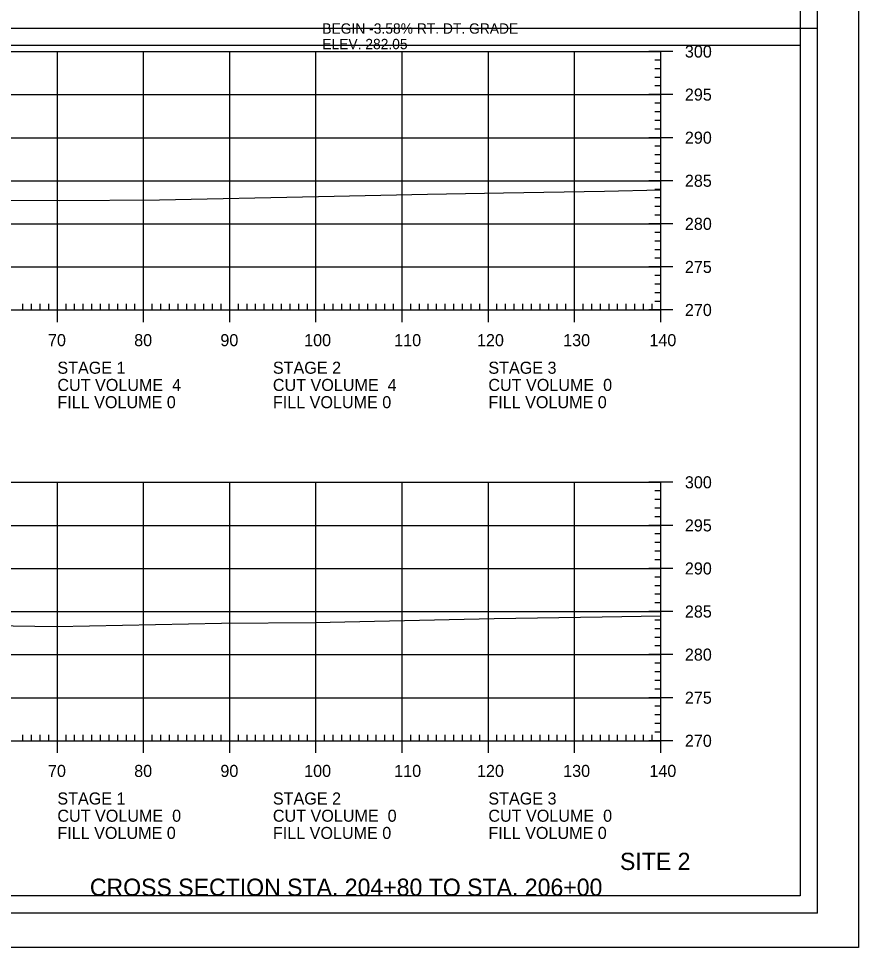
# Model space of a CAD drawing. Extents: x 1368713 to 1370673, y 380279 to 380950.
# Drawn here: x 1370575.1 to 1370672.6, y 380310.4 to 380418.2 of the extents above; entities that cross this region are included whole.
import ezdxf

# ---------------------------------------------------------------- set-up
doc = ezdxf.new("R2010")
doc.units = 0
for name, color, linetype in [('Notes', 7, 'Continuous'), ('R_Axis', 7, 'Continuous'), ('R_Axis Annot', 7, 'Continuous'), ('R_Border', 7, 'Continuous'), ('R_Border Plan-Plan', 7, 'Continuous'), ('R_Draft', 7, 'Continuous'), ('R_Exist Surface', 7, 'Continuous'), ('R_Grid', 7, 'Continuous'), ('R_No Plot', 7, 'Continuous')]:
    doc.layers.add(name, color=color, linetype=linetype)

msp = doc.modelspace()

# ---------------------------------------------------------------- linework, layer by layer
at = {"layer": 'R_Axis'}
for p, q in [((1370651.03, 380414.42), (1370648.23, 380414.42)), ((1370649.63, 380384.42), (1370649.63, 380414.42)), ((1370649.63, 380413.42), (1370648.93, 380413.42)), ((1370649.63, 380412.42), (1370648.93, 380412.42)), ((1370649.63, 380411.42), (1370648.93, 380411.42)), ((1370649.63, 380410.42), (1370648.93, 380410.42)), ((1370651.03, 380409.42), (1370648.23, 380409.42)), ((1370649.63, 380408.42), (1370648.93, 380408.42)), ((1370649.63, 380407.42), (1370648.93, 380407.42)), ((1370649.63, 380406.42), (1370648.93, 380406.42)), ((1370649.63, 380405.42), (1370648.93, 380405.42)), ((1370651.03, 380404.42), (1370648.23, 380404.42)), ((1370649.63, 380403.42), (1370648.93, 380403.42)), ((1370649.63, 380402.42), (1370648.93, 380402.42)), ((1370649.63, 380401.42), (1370648.93, 380401.42)), ((1370651.03, 380399.42), (1370648.23, 380399.42)), ((1370649.63, 380400.42), (1370648.93, 380400.42)), ((1370649.63, 380398.42), (1370648.93, 380398.42)), ((1370649.63, 380397.42), (1370648.93, 380397.42)), ((1370649.63, 380396.42), (1370648.93, 380396.42)), ((1370649.63, 380395.42), (1370648.93, 380395.42)), ((1370651.03, 380394.42), (1370648.23, 380394.42)), ((1370649.63, 380393.42), (1370648.93, 380393.42)), ((1370649.63, 380392.42), (1370648.93, 380392.42)), ((1370649.63, 380391.42), (1370648.93, 380391.42)), ((1370649.63, 380390.42), (1370648.93, 380390.42)), ((1370651.03, 380389.42), (1370648.23, 380389.42)), ((1370649.63, 380388.42), (1370648.93, 380388.42)), ((1370649.63, 380387.42), (1370648.93, 380387.42)), ((1370579.63, 380383.02), (1370579.63, 380385.82)), ((1370589.63, 380383.02), (1370589.63, 380385.82)), ((1370599.63, 380383.02), (1370599.63, 380385.82)), ((1370609.63, 380383.02), (1370609.63, 380385.82)), ((1370619.63, 380383.02), (1370619.63, 380385.82)), ((1370629.63, 380383.02), (1370629.63, 380385.82)), ((1370639.63, 380383.02), (1370639.63, 380385.82)), ((1370649.63, 380386.42), (1370648.93, 380386.42)), ((1370649.63, 380385.42), (1370648.93, 380385.42)), ((1370649.63, 380383.02), (1370649.63, 380385.82)), ((1370369.63, 380384.42), (1370649.63, 380384.42)), ((1370575.63, 380384.42), (1370575.63, 380385.12)), ((1370576.63, 380384.42), (1370576.63, 380385.12)), ((1370577.63, 380384.42), (1370577.63, 380385.12)), ((1370578.63, 380384.42), (1370578.63, 380385.12)), ((1370580.63, 380384.42), (1370580.63, 380385.12)), ((1370581.63, 380384.42), (1370581.63, 380385.12)), ((1370582.63, 380384.42), (1370582.63, 380385.12)), ((1370583.63, 380384.42), (1370583.63, 380385.12)), ((1370584.63, 380384.42), (1370584.63, 380385.12)), ((1370585.63, 380384.42), (1370585.63, 380385.12)), ((1370586.63, 380384.42), (1370586.63, 380385.12)), ((1370587.63, 380384.42), (1370587.63, 380385.12)), ((1370588.63, 380384.42), (1370588.63, 380385.12)), ((1370590.63, 380384.42), (1370590.63, 380385.12)), ((1370591.63, 380384.42), (1370591.63, 380385.12)), ((1370592.63, 380384.42), (1370592.63, 380385.12)), ((1370593.63, 380384.42), (1370593.63, 380385.12)), ((1370594.63, 380384.42), (1370594.63, 380385.12)), ((1370595.63, 380384.42), (1370595.63, 380385.12)), ((1370596.63, 380384.42), (1370596.63, 380385.12)), ((1370597.63, 380384.42), (1370597.63, 380385.12)), ((1370598.63, 380384.42), (1370598.63, 380385.12)), ((1370600.63, 380384.42), (1370600.63, 380385.12)), ((1370601.63, 380384.42), (1370601.63, 380385.12)), ((1370602.63, 380384.42), (1370602.63, 380385.12)), ((1370603.63, 380384.42), (1370603.63, 380385.12)), ((1370604.63, 380384.42), (1370604.63, 380385.12)), ((1370605.63, 380384.42), (1370605.63, 380385.12)), ((1370606.63, 380384.42), (1370606.63, 380385.12)), ((1370607.63, 380384.42), (1370607.63, 380385.12)), ((1370608.63, 380384.42), (1370608.63, 380385.12)), ((1370610.63, 380384.42), (1370610.63, 380385.12)), ((1370611.63, 380384.42), (1370611.63, 380385.12)), ((1370612.63, 380384.42), (1370612.63, 380385.12)), ((1370613.63, 380384.42), (1370613.63, 380385.12)), ((1370614.63, 380384.42), (1370614.63, 380385.12)), ((1370615.63, 380384.42), (1370615.63, 380385.12)), ((1370616.63, 380384.42), (1370616.63, 380385.12)), ((1370617.63, 380384.42), (1370617.63, 380385.12)), ((1370618.63, 380384.42), (1370618.63, 380385.12)), ((1370620.63, 380384.42), (1370620.63, 380385.12)), ((1370621.63, 380384.42), (1370621.63, 380385.12)), ((1370622.63, 380384.42), (1370622.63, 380385.12)), ((1370623.63, 380384.42), (1370623.63, 380385.12)), ((1370624.63, 380384.42), (1370624.63, 380385.12)), ((1370625.63, 380384.42), (1370625.63, 380385.12)), ((1370626.63, 380384.42), (1370626.63, 380385.12)), ((1370627.63, 380384.42), (1370627.63, 380385.12)), ((1370628.63, 380384.42), (1370628.63, 380385.12)), ((1370630.63, 380384.42), (1370630.63, 380385.12)), ((1370631.63, 380384.42), (1370631.63, 380385.12)), ((1370632.63, 380384.42), (1370632.63, 380385.12)), ((1370633.63, 380384.42), (1370633.63, 380385.12)), ((1370634.63, 380384.42), (1370634.63, 380385.12)), ((1370635.63, 380384.42), (1370635.63, 380385.12)), ((1370636.63, 380384.42), (1370636.63, 380385.12)), ((1370637.63, 380384.42), (1370637.63, 380385.12)), ((1370638.63, 380384.42), (1370638.63, 380385.12)), ((1370640.63, 380384.42), (1370640.63, 380385.12)), ((1370641.63, 380384.42), (1370641.63, 380385.12)), ((1370642.63, 380384.42), (1370642.63, 380385.12)), ((1370643.63, 380384.42), (1370643.63, 380385.12)), ((1370644.63, 380384.42), (1370644.63, 380385.12)), ((1370645.63, 380384.42), (1370645.63, 380385.12)), ((1370646.63, 380384.42), (1370646.63, 380385.12)), ((1370647.63, 380384.42), (1370647.63, 380385.12)), ((1370651.03, 380384.42), (1370648.23, 380384.42)), ((1370648.63, 380384.42), (1370648.63, 380385.12)), ((1370651.03, 380364.42), (1370648.23, 380364.42)), ((1370649.63, 380334.42), (1370649.63, 380364.42)), ((1370649.63, 380363.42), (1370648.93, 380363.42)), ((1370649.63, 380362.42), (1370648.93, 380362.42)), ((1370649.63, 380361.42), (1370648.93, 380361.42)), ((1370649.63, 380360.42), (1370648.93, 380360.42)), ((1370651.03, 380359.42), (1370648.23, 380359.42)), ((1370649.63, 380358.42), (1370648.93, 380358.42)), ((1370649.63, 380357.42), (1370648.93, 380357.42)), ((1370649.63, 380356.42), (1370648.93, 380356.42)), ((1370649.63, 380355.42), (1370648.93, 380355.42)), ((1370651.03, 380354.42), (1370648.23, 380354.42)), ((1370649.63, 380353.42), (1370648.93, 380353.42)), ((1370649.63, 380352.42), (1370648.93, 380352.42)), ((1370649.63, 380351.42), (1370648.93, 380351.42)), ((1370649.63, 380350.42), (1370648.93, 380350.42)), ((1370651.03, 380349.42), (1370648.23, 380349.42)), ((1370649.63, 380348.42), (1370648.93, 380348.42)), ((1370649.63, 380347.42), (1370648.93, 380347.42)), ((1370649.63, 380346.42), (1370648.93, 380346.42)), ((1370649.63, 380345.42), (1370648.93, 380345.42)), ((1370651.03, 380344.42), (1370648.23, 380344.42)), ((1370649.63, 380343.42), (1370648.93, 380343.42)), ((1370649.63, 380342.42), (1370648.93, 380342.42)), ((1370649.63, 380341.42), (1370648.93, 380341.42)), ((1370649.63, 380340.42), (1370648.93, 380340.42)), ((1370651.03, 380339.42), (1370648.23, 380339.42)), ((1370649.63, 380338.42), (1370648.93, 380338.42)), ((1370649.63, 380337.42), (1370648.93, 380337.42)), ((1370579.63, 380333.02), (1370579.63, 380335.82)), ((1370589.63, 380333.02), (1370589.63, 380335.82)), ((1370599.63, 380333.02), (1370599.63, 380335.82)), ((1370609.63, 380333.02), (1370609.63, 380335.82)), ((1370619.63, 380333.02), (1370619.63, 380335.82)), ((1370629.63, 380333.02), (1370629.63, 380335.82)), ((1370639.63, 380333.02), (1370639.63, 380335.82)), ((1370649.63, 380336.42), (1370648.93, 380336.42)), ((1370649.63, 380333.02), (1370649.63, 380335.82)), ((1370575.63, 380334.42), (1370575.63, 380335.12)), ((1370576.63, 380334.42), (1370576.63, 380335.12)), ((1370577.63, 380334.42), (1370577.63, 380335.12)), ((1370578.63, 380334.42), (1370578.63, 380335.12)), ((1370580.63, 380334.42), (1370580.63, 380335.12)), ((1370581.63, 380334.42), (1370581.63, 380335.12)), ((1370582.63, 380334.42), (1370582.63, 380335.12)), ((1370583.63, 380334.42), (1370583.63, 380335.12)), ((1370584.63, 380334.42), (1370584.63, 380335.12)), ((1370585.63, 380334.42), (1370585.63, 380335.12)), ((1370586.63, 380334.42), (1370586.63, 380335.12)), ((1370587.63, 380334.42), (1370587.63, 380335.12)), ((1370588.63, 380334.42), (1370588.63, 380335.12)), ((1370590.63, 380334.42), (1370590.63, 380335.12)), ((1370591.63, 380334.42), (1370591.63, 380335.12)), ((1370592.63, 380334.42), (1370592.63, 380335.12)), ((1370593.63, 380334.42), (1370593.63, 380335.12)), ((1370594.63, 380334.42), (1370594.63, 380335.12)), ((1370595.63, 380334.42), (1370595.63, 380335.12)), ((1370596.63, 380334.42), (1370596.63, 380335.12)), ((1370597.63, 380334.42), (1370597.63, 380335.12)), ((1370598.63, 380334.42), (1370598.63, 380335.12)), ((1370600.63, 380334.42), (1370600.63, 380335.12)), ((1370601.63, 380334.42), (1370601.63, 380335.12)), ((1370602.63, 380334.42), (1370602.63, 380335.12)), ((1370603.63, 380334.42), (1370603.63, 380335.12)), ((1370604.63, 380334.42), (1370604.63, 380335.12)), ((1370605.63, 380334.42), (1370605.63, 380335.12)), ((1370606.63, 380334.42), (1370606.63, 380335.12)), ((1370607.63, 380334.42), (1370607.63, 380335.12)), ((1370608.63, 380334.42), (1370608.63, 380335.12)), ((1370610.63, 380334.42), (1370610.63, 380335.12)), ((1370611.63, 380334.42), (1370611.63, 380335.12)), ((1370612.63, 380334.42), (1370612.63, 380335.12)), ((1370613.63, 380334.42), (1370613.63, 380335.12)), ((1370614.63, 380334.42), (1370614.63, 380335.12)), ((1370615.63, 380334.42), (1370615.63, 380335.12)), ((1370616.63, 380334.42), (1370616.63, 380335.12)), ((1370617.63, 380334.42), (1370617.63, 380335.12)), ((1370618.63, 380334.42), (1370618.63, 380335.12)), ((1370620.63, 380334.42), (1370620.63, 380335.12)), ((1370621.63, 380334.42), (1370621.63, 380335.12)), ((1370622.63, 380334.42), (1370622.63, 380335.12)), ((1370623.63, 380334.42), (1370623.63, 380335.12)), ((1370624.63, 380334.42), (1370624.63, 380335.12)), ((1370625.63, 380334.42), (1370625.63, 380335.12)), ((1370626.63, 380334.42), (1370626.63, 380335.12)), ((1370627.63, 380334.42), (1370627.63, 380335.12)), ((1370628.63, 380334.42), (1370628.63, 380335.12)), ((1370630.63, 380334.42), (1370630.63, 380335.12)), ((1370631.63, 380334.42), (1370631.63, 380335.12)), ((1370632.63, 380334.42), (1370632.63, 380335.12)), ((1370633.63, 380334.42), (1370633.63, 380335.12)), ((1370634.63, 380334.42), (1370634.63, 380335.12)), ((1370635.63, 380334.42), (1370635.63, 380335.12)), ((1370636.63, 380334.42), (1370636.63, 380335.12)), ((1370637.63, 380334.42), (1370637.63, 380335.12)), ((1370638.63, 380334.42), (1370638.63, 380335.12)), ((1370640.63, 380334.42), (1370640.63, 380335.12)), ((1370641.63, 380334.42), (1370641.63, 380335.12)), ((1370642.63, 380334.42), (1370642.63, 380335.12)), ((1370643.63, 380334.42), (1370643.63, 380335.12)), ((1370644.63, 380334.42), (1370644.63, 380335.12)), ((1370645.63, 380334.42), (1370645.63, 380335.12)), ((1370646.63, 380334.42), (1370646.63, 380335.12)), ((1370647.63, 380334.42), (1370647.63, 380335.12)), ((1370648.63, 380334.42), (1370648.63, 380335.12)), ((1370649.63, 380335.42), (1370648.93, 380335.42)), ((1370369.63, 380334.42), (1370649.63, 380334.42)), ((1370651.03, 380334.42), (1370648.23, 380334.42))]:
    msp.add_line(p, q, dxfattribs=at)
at = {"layer": 'R_Border'}
for q in [(1370667.81, 380519.88), (1370351.63, 380314.42)]:
    msp.add_line((1370667.81, 380314.42), q, dxfattribs=at)
at = {"layer": 'R_Border Plan-Plan'}
msp.add_line((1370351.63, 380417.15), (1370667.81, 380417.15), dxfattribs=at)
at = {"layer": 'R_Exist Surface'}
for points in [[(1370568.12, 380397.21), (1370579.92, 380397.13), (1370591.49, 380397.22), (1370609.92, 380397.59), (1370622.57, 380397.87), (1370631.38, 380398.03), (1370643.1, 380398.22), (1370649.63, 380398.35)], [(1370559.39, 380347.99), (1370579.53, 380347.69), (1370598.68, 380348.06), (1370609.53, 380348.13), (1370618.16, 380348.35), (1370630.29, 380348.62), (1370642.84, 380348.81), (1370649.63, 380348.93)]]:
    msp.add_lwpolyline(points, dxfattribs=at)
at = {"layer": 'R_Grid'}
for p, q in [((1370369.63, 380414.42), (1370649.63, 380414.42)), ((1370579.63, 380384.42), (1370579.63, 380414.42)), ((1370589.63, 380384.42), (1370589.63, 380414.42)), ((1370599.63, 380384.42), (1370599.63, 380414.42)), ((1370609.63, 380384.42), (1370609.63, 380414.42)), ((1370619.63, 380384.42), (1370619.63, 380414.42)), ((1370629.63, 380384.42), (1370629.63, 380414.42)), ((1370639.63, 380384.42), (1370639.63, 380414.42)), ((1370649.63, 380384.42), (1370649.63, 380414.42)), ((1370369.63, 380409.42), (1370649.63, 380409.42)), ((1370369.63, 380404.42), (1370649.63, 380404.42)), ((1370369.63, 380399.42), (1370649.63, 380399.42)), ((1370369.63, 380394.42), (1370649.63, 380394.42)), ((1370369.63, 380389.42), (1370649.63, 380389.42)), ((1370369.63, 380384.42), (1370649.63, 380384.42)), ((1370369.63, 380364.42), (1370649.63, 380364.42)), ((1370579.63, 380334.42), (1370579.63, 380364.42)), ((1370589.63, 380334.42), (1370589.63, 380364.42)), ((1370599.63, 380334.42), (1370599.63, 380364.42)), ((1370609.63, 380334.42), (1370609.63, 380364.42)), ((1370619.63, 380334.42), (1370619.63, 380364.42)), ((1370629.63, 380334.42), (1370629.63, 380364.42)), ((1370639.63, 380334.42), (1370639.63, 380364.42)), ((1370649.63, 380334.42), (1370649.63, 380364.42)), ((1370369.63, 380359.42), (1370649.63, 380359.42)), ((1370369.63, 380354.42), (1370649.63, 380354.42)), ((1370369.63, 380349.42), (1370649.63, 380349.42)), ((1370369.63, 380344.42), (1370649.63, 380344.42)), ((1370369.63, 380339.42), (1370649.63, 380339.42)), ((1370369.63, 380334.42), (1370649.63, 380334.42))]:
    msp.add_line(p, q, dxfattribs=at)
at = {"layer": 'R_No Plot'}
for points in [[(1370339.22, 380523.77), (1370672.56, 380523.77), (1370672.56, 380310.43), (1370339.22, 380310.43)], [(1370353.63, 380517.88), (1370603.17, 380517.88), (1370603.17, 380508), (1370620.71, 380508), (1370644.81, 380508), (1370644.81, 380485.66), (1370665.81, 380485.66), (1370665.81, 380316.42), (1370353.63, 380316.42)], [(1370353.63, 380415.15), (1370665.81, 380415.15), (1370665.81, 380316.42), (1370353.63, 380316.42)]]:
    msp.add_lwpolyline(points, close=True, dxfattribs=at)

# ---------------------------------------------------------------- texts
at = {"layer": 'Notes'}
for s, p in [('BEGIN -3.58% RT. DT. GRADE', (1370610.36, 380416.49)), ('ELEV. 282.05', (1370610.36, 380414.69))]:
    msp.add_text(s, height=1.2, dxfattribs=at).set_placement(p)
at = {"layer": 'R_Axis Annot'}
for s, p in [('300', (1370652.43, 380413.72)), ('295', (1370652.43, 380408.72)), ('290', (1370652.43, 380403.72)), ('285', (1370652.43, 380398.72)), ('280', (1370652.43, 380393.72)), ('275', (1370652.43, 380388.72)), ('270', (1370652.43, 380383.72)), ('70', (1370578.54, 380380.22)), ('80', (1370588.54, 380380.22)), ('90', (1370598.54, 380380.22)), ('100', (1370608.26, 380380.22)), ('110', (1370618.71, 380380.22)), ('120', (1370628.31, 380380.22)), ('130', (1370638.31, 380380.22)), ('140', (1370648.31, 380380.22)), ('STAGE 1', (1370579.63, 380377.02)), ('STAGE 2', (1370604.63, 380377.02)), ('STAGE 3', (1370629.63, 380377.02)), ('CUT VOLUME  4', (1370579.63, 380375.02)), ('CUT VOLUME  4', (1370604.63, 380375.02)), ('CUT VOLUME  0', (1370629.63, 380375.02)), ('FILL VOLUME 0', (1370579.63, 380373.02)), ('FILL VOLUME 0', (1370604.63, 380373.02)), ('FILL VOLUME 0', (1370629.63, 380373.02)), ('300', (1370652.43, 380363.72)), ('295', (1370652.43, 380358.72)), ('290', (1370652.43, 380353.72)), ('285', (1370652.43, 380348.72)), ('280', (1370652.43, 380343.72)), ('275', (1370652.43, 380338.72)), ('270', (1370652.43, 380333.72)), ('70', (1370578.54, 380330.22)), ('80', (1370588.54, 380330.22)), ('90', (1370598.54, 380330.22)), ('100', (1370608.26, 380330.22)), ('110', (1370618.71, 380330.22)), ('120', (1370628.31, 380330.22)), ('130', (1370638.31, 380330.22)), ('140', (1370648.31, 380330.22)), ('STAGE 1', (1370579.63, 380327.02)), ('STAGE 2', (1370604.63, 380327.02)), ('STAGE 3', (1370629.63, 380327.02)), ('CUT VOLUME  0', (1370579.63, 380325.02)), ('CUT VOLUME  0', (1370604.63, 380325.02)), ('CUT VOLUME  0', (1370629.63, 380325.02)), ('FILL VOLUME 0', (1370579.63, 380323.02)), ('FILL VOLUME 0', (1370604.63, 380323.02)), ('FILL VOLUME 0', (1370629.63, 380323.02))]:
    msp.add_text(s, height=1.4, dxfattribs=at).set_placement(p)
at = {"layer": 'R_Draft'}
for s, p in [('SITE 2', (1370644.9, 380319.42)), ('CROSS SECTION STA. 204+80 TO STA. 206+00', (1370583.4, 380316.42))]:
    msp.add_text(s, height=2, dxfattribs=at).set_placement(p)

doc.saveas('drawing.dxf')
